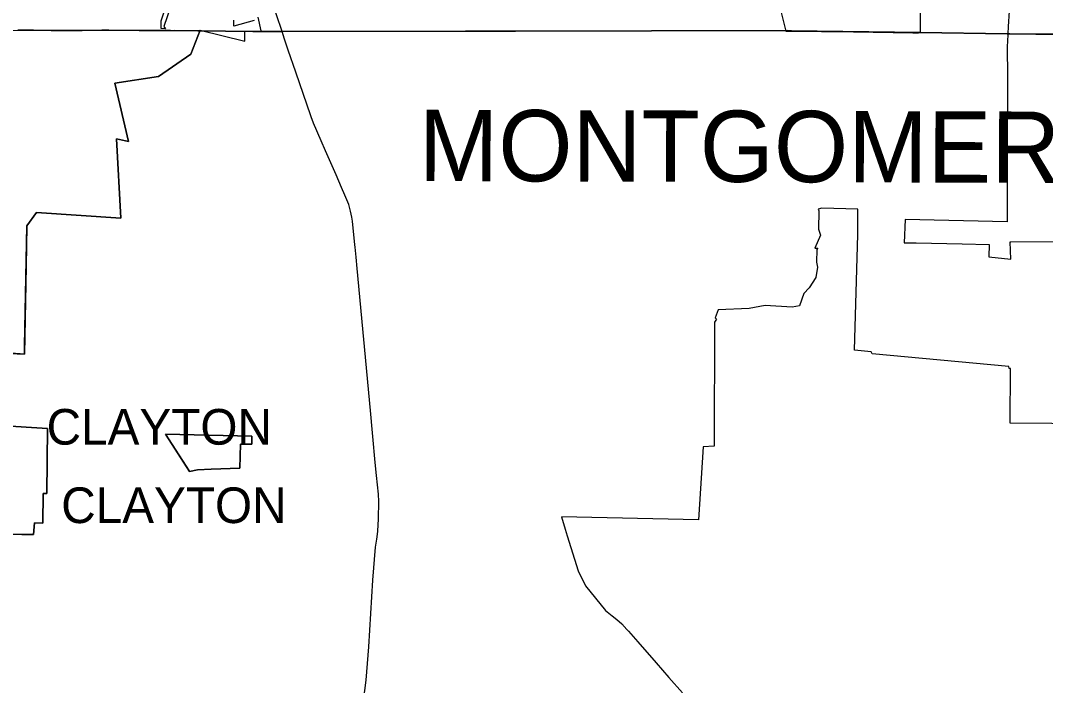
# Model space of a CAD drawing. Extents: x 0 to 34, y 0 to 22.
# Drawn here: x 4.7212 to 4.9522, y 15.9787 to 16.1285 of the extents above; entities that cross this region are included whole.
import ezdxf

# ---------------------------------------------------------------- set-up
doc = ezdxf.new("R2010")
doc.units = 0
for name, color, linetype in [('GM_X_Corporation', 7, 'Continuous'), ('GM_X_Corporation_Text', 7, 'Continuous'), ('GM_X_County', 7, 'Continuous'), ('GM_X_County_Text', 7, 'Continuous'), ('GM_X_State_Route', 7, 'Continuous')]:
    doc.layers.add(name, color=color, linetype=linetype)

msp = doc.modelspace()

# ---------------------------------------------------------------- linework, layer by layer
at = {"layer": 'GM_X_Corporation'}
for points in [[(4.89036, 16.13944), (4.89367, 16.12612), (4.89406, 16.12612), (4.89449, 16.12611), (4.90891, 16.12594), (4.92225, 16.12577), (4.92225, 16.12577), (4.92352, 16.12576), (4.92401, 16.12579), (4.92401, 16.13828)], [(4.75499, 16.13133), (4.75353, 16.12714), (4.75394, 16.12666), (4.75297, 16.12673), (4.75297, 16.12847), (4.75353, 16.13028)], [(4.94401, 16.13064), (4.94373, 16.12716), (4.94369, 16.12548), (4.94366, 16.12508), (4.94364, 16.1249), (4.94361, 16.12431), (4.94358, 16.12373), (4.94356, 16.12283), (4.94356, 16.12222), (4.94356, 16.12162), (4.94358, 16.11691), (4.94358, 16.11688), (4.94358, 16.11671), (4.94358, 16.11559), (4.94359, 16.11446), (4.94359, 16.11246), (4.94357, 16.10682), (4.94356, 16.10577), (4.94356, 16.1018), (4.94355, 16.10131), (4.94349, 16.08314), (4.92053, 16.08368), (4.92032, 16.07844), (4.92303, 16.07838), (4.93339, 16.07818), (4.93947, 16.07806), (4.93939, 16.07527), (4.94437, 16.07477), (4.94423, 16.07863), (4.94438, 16.07863), (4.97352, 16.07871)], [(4.71718, 16.05356), (4.72217, 16.05329), (4.72217, 16.0552), (4.72264, 16.08225), (4.72482, 16.08525), (4.74384, 16.08397), (4.74289, 16.10187), (4.74561, 16.10124), (4.74247, 16.11443), (4.75235, 16.11593), (4.75963, 16.12092), (4.76169, 16.12634), (4.77178, 16.12385), (4.77178, 16.12615), (4.7755, 16.12623), (4.7748, 16.12924)], [(4.7739, 16.12854), (4.76929, 16.12721), (4.76929, 16.12861)], [(4.70734, 16.12633), (4.72913, 16.12627), (4.72937, 16.12627), (4.756, 16.12631), (4.7576, 16.1263), (4.76169, 16.12634), (4.75963, 16.12092), (4.75235, 16.11593), (4.74247, 16.11443), (4.74561, 16.10124), (4.74289, 16.10187), (4.74384, 16.08397), (4.72482, 16.08525), (4.72264, 16.08225), (4.72256, 16.07317), (4.72217, 16.05329), (4.7171, 16.05369)], [(4.98174, 16.03747), (4.94419, 16.03774), (4.94428, 16.05009), (4.94395, 16.05006), (4.94392, 16.05051), (4.91309, 16.05342), (4.91291, 16.05387), (4.90913, 16.05426), (4.90988, 16.08027), (4.90991, 16.08602), (4.90175, 16.08623), (4.90094, 16.08599), (4.90109, 16.08563), (4.90101, 16.08147), (4.90148, 16.08015), (4.90022, 16.07724), (4.90086, 16.0772), (4.90061, 16.07694), (4.90058, 16.07409), (4.90082, 16.07292), (4.90043, 16.07064), (4.8989, 16.0683), (4.89774, 16.06698), (4.89675, 16.06422), (4.89511, 16.06393), (4.88901, 16.06431), (4.88541, 16.06359), (4.87845, 16.06332), (4.87773, 16.06152), (4.87803, 16.06119), (4.87758, 16.06053), (4.87754, 16.03259), (4.87501, 16.03244), (4.87397, 16.01597), (4.84313, 16.01666), (4.84398, 16.01385), (4.8444, 16.01235), (4.84691, 16.00452), (4.84854, 16.00111), (4.85301, 15.99555), (4.85452, 15.99435), (4.85557, 15.99351), (4.85673, 15.99258), (4.85784, 15.99131), (4.85805, 15.99107), (4.85815, 15.99095), (4.85821, 15.99089), (4.85978, 15.9891), (4.8603, 15.9885), (4.86443, 15.98379), (4.86733, 15.98048), (4.87038, 15.97701)], [(4.71937, 16.01274), (4.72157, 16.01271), (4.72419, 16.01268), (4.72443, 16.01528), (4.7263, 16.01521), (4.72634, 16.02193), (4.7272, 16.0219), (4.72734, 16.03661), (4.71655, 16.03724)], [(4.71655, 16.03724), (4.72734, 16.03661), (4.7272, 16.0219), (4.72634, 16.02193), (4.7263, 16.01521), (4.72443, 16.01528), (4.72419, 16.01268), (4.71937, 16.01274)]]:
    msp.add_lwpolyline(points, dxfattribs=at)
for points in [[(4.77065, 16.02767), (4.77084, 16.03308), (4.77338, 16.03301), (4.77339, 16.03484), (4.75394, 16.03529), (4.75925, 16.02706), (4.75933, 16.02692), (4.76114, 16.02729), (4.76417, 16.02741)], [(4.75394, 16.03529), (4.77339, 16.03484), (4.77338, 16.03301), (4.77084, 16.03308), (4.77065, 16.02767), (4.76417, 16.02741), (4.76114, 16.02729), (4.75933, 16.02692)]]:
    msp.add_lwpolyline(points, close=True, dxfattribs=at)
at = {"layer": 'GM_X_County'}
for points in [[(4.72062, 16.12633), (4.7242, 16.12633), (4.72815, 16.12629), (4.72941, 16.12628), (4.73189, 16.12628), (4.73511, 16.1263), (4.7396, 16.12634), (4.74113, 16.12635), (4.748, 16.12628), (4.74934, 16.12628), (4.75152, 16.12628), (4.75352, 16.12629), (4.75507, 16.12629), (4.77361, 16.12608), (4.78016, 16.12608), (4.82152, 16.12611), (4.82541, 16.12611), (4.83274, 16.12611), (4.89403, 16.12625), (4.89491, 16.12623), (4.92395, 16.12579), (4.94355, 16.12552), (4.94414, 16.12549), (4.94998, 16.12546), (4.95431, 16.12546)], [(4.95431, 16.12546), (4.94998, 16.12546), (4.94414, 16.12549), (4.94355, 16.12552), (4.92395, 16.12579), (4.89491, 16.12623), (4.89403, 16.12625), (4.83274, 16.12611), (4.82541, 16.12611), (4.82152, 16.12611), (4.78016, 16.12608), (4.77361, 16.12608), (4.75507, 16.12629), (4.75352, 16.12629), (4.75152, 16.12628), (4.74934, 16.12628), (4.748, 16.12628), (4.74113, 16.12635), (4.7396, 16.12634), (4.73511, 16.1263), (4.73189, 16.12628), (4.72941, 16.12628), (4.72815, 16.12629), (4.7242, 16.12633), (4.72062, 16.12633)]]:
    msp.add_lwpolyline(points, dxfattribs=at)
at = {"layer": 'GM_X_State_Route'}
msp.add_line((4.80052, 16.03561), (4.80006, 16.0406), dxfattribs=at)
for points in [[(4.78018, 16.12603), (4.77893, 16.12977), (4.77795, 16.13266), (4.77714, 16.13513)], [(4.78666, 16.10704), (4.78328, 16.11691), (4.78157, 16.12183), (4.7807, 16.12433), (4.78018, 16.12603)], [(4.79659, 16.078), (4.79606, 16.08329), (4.79591, 16.08423), (4.7956, 16.08554), (4.79519, 16.08704), (4.79433, 16.08913), (4.7936, 16.09088), (4.79235, 16.09374), (4.78996, 16.09913), (4.78896, 16.1014), (4.78725, 16.10536), (4.78674, 16.10681), (4.78666, 16.10704)], [(4.80006, 16.0406), (4.79708, 16.07265), (4.79684, 16.07515), (4.79665, 16.07741), (4.79659, 16.078)], [(4.79837, 15.97141), (4.79862, 15.97583), (4.79879, 15.97751), (4.79909, 15.97985), (4.79973, 15.98737), (4.80063, 16.00242), (4.80119, 16.00986), (4.80153, 16.01167), (4.80164, 16.01276), (4.80172, 16.01343), (4.80191, 16.0162), (4.80195, 16.02015), (4.80187, 16.02175), (4.80146, 16.02598), (4.80114, 16.02891), (4.8006, 16.03477), (4.80052, 16.03561)]]:
    msp.add_lwpolyline(points, dxfattribs=at)

# ---------------------------------------------------------------- texts
at = {"layer": 'GM_X_Corporation_Text'}
for p in [(4.72713, 16.03293), (4.73042, 16.01526)]:
    msp.add_text('CLAYTON', height=0.008037, rotation=0, dxfattribs=at).set_placement(p)
at = {"layer": 'GM_X_County_Text'}
msp.add_text('MONTGOMERY COUNTY', height=0.016074, rotation=359.824, dxfattribs=at).set_placement((4.81096, 16.09235))

doc.saveas('drawing.dxf')
